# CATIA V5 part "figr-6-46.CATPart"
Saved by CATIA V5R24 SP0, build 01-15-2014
Part number: Part1
Bounding box of the stored display mesh (mm): x -26.811 to 26.811, y -47.298 to 47.298, z 0 to 31.431
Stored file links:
  D:\KAVITA\CATIA V5-6R2014 Project_ Kavita\CATIA V5-6R2014_partfiles\Partfiles\c06_catia_v5-6r2014_prt\figr-6-46.CATPart
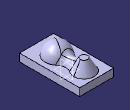
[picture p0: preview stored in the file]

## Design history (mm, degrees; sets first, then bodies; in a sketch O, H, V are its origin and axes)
Body1 (main body)
  Sketch1 on xy-plane, origin (0, 0, 0), H (1, 0, 0), V (0, 1, 0)
    line L1 (-26.8114, 47.2981) -> (26.8114, 47.2981)
    line L2 (26.8114, 47.2981) -> (26.8114, -47.2981)
    line L3 (26.8114, -47.2981) -> (-26.8114, -47.2981)
    line L4 (-26.8114, -47.2981) -> (-26.8114, 47.2981)
    axis line L5 (26.8114, -47.2981) -> (-26.8114, 47.2981)
    horizontal: L1 H, L3 H
    vertical: L2 V, L4 V
    coincidence: L5 O
    midpoint: L5 O
  Pad1: profile Sketch1, direction (0, 0, 1), length 12
  Sketch2 on yz-plane, origin (0, 0, 0), H (0, 1, 0), V (0, 0, 1)
    axis line L1 (-14.846, 35.4307) -> (-14.846, -5.9324)
    arc A1 centre (-14.846, 12.2093) radius 19.2216 from (-14.846, 31.431) to (-33.1926, 6.476) ccw
    point P3 (-14.846, 12.2093)
    point P4 (-14.846, 31.431)
    line L2 (-14.846, 31.431) -> (-14.846, 8.3996)
    line L3 (-14.846, 8.3996) -> (-33.1926, 6.476)
    vertical: L1 V, L2 V
    coincidence: P3 L1, P4 L1, A1 O
  Shaft1: profile Sketch2, axis Sketch2.L1, angle 360
  Sketch3 on face of Pad1, origin (0, 0, 12), H (1, 0, 0), V (0, 1, 0)
    circle A1 centre (0, 27.4246) radius 16.1543
    point P1 (0, 27.4246)
    coincidence: P1 V
  Pad2: profile Sketch3, direction (0, 0, 1), length 18
  Draft1: Angle 30, Neutral face of Pad1, PullDir face of Pad1, SupportToDraft face of Pad2
  FaceFillet1: Face1 face of Shaft1, Face2 face of Pad2, Radius 15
